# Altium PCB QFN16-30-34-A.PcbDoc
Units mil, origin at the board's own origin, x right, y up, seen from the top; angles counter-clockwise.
Board outline 1200 x 3800 mil, 4 copper layers (Top Layer, Metal 2, Metal 3, Bottom Layer), stack 61.6 mil thick; 25 components, 16 nets, 109 pads, 567 vias.
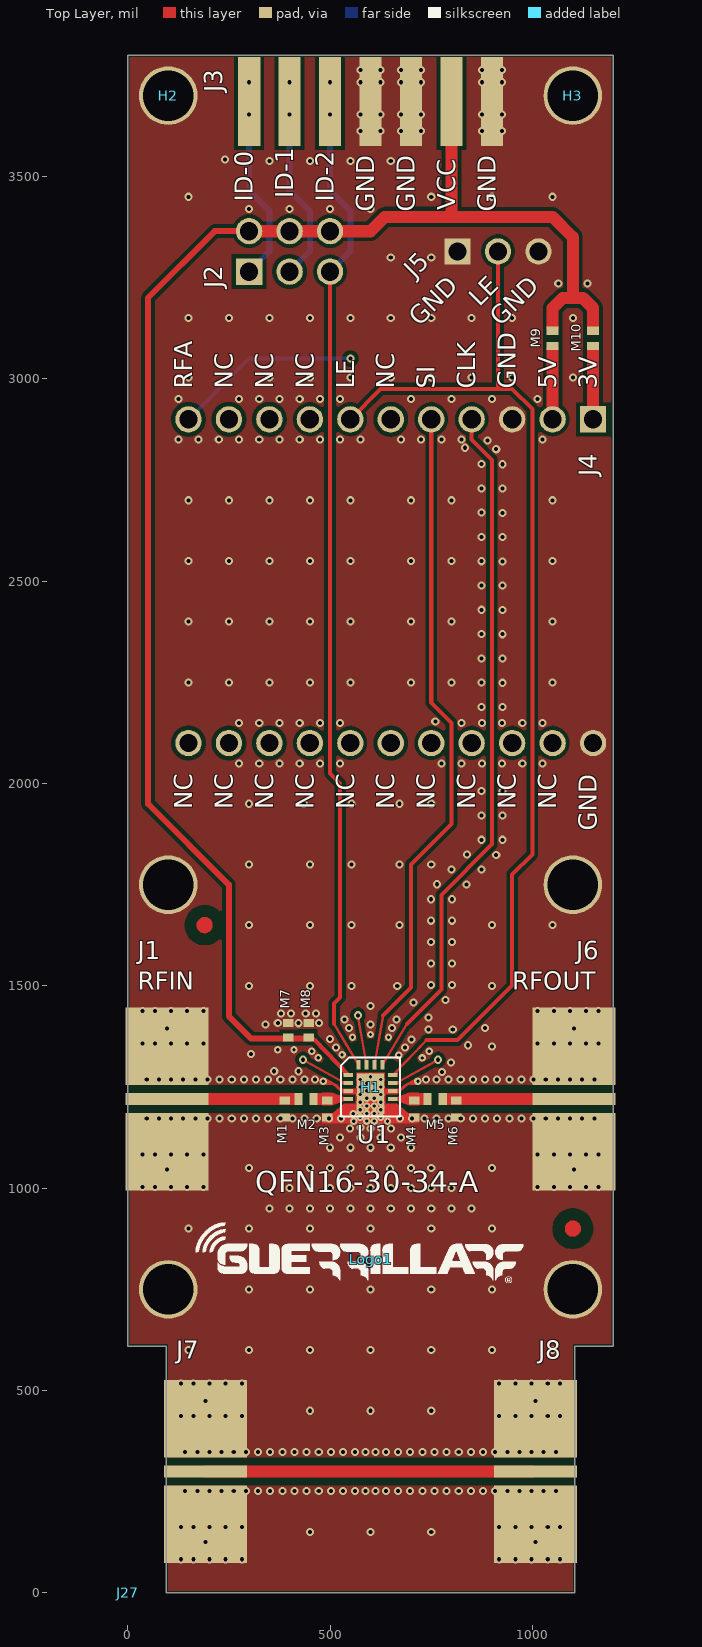
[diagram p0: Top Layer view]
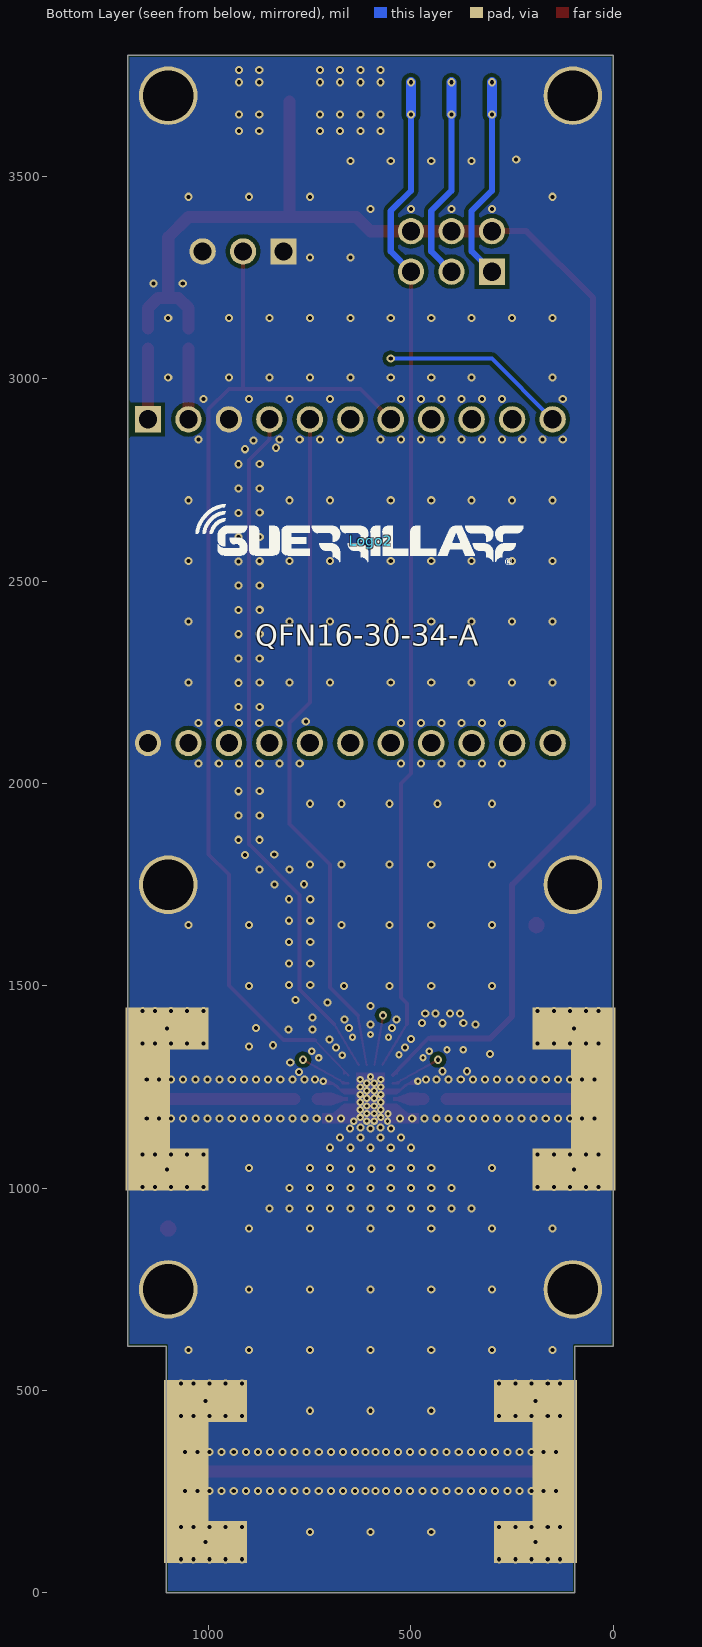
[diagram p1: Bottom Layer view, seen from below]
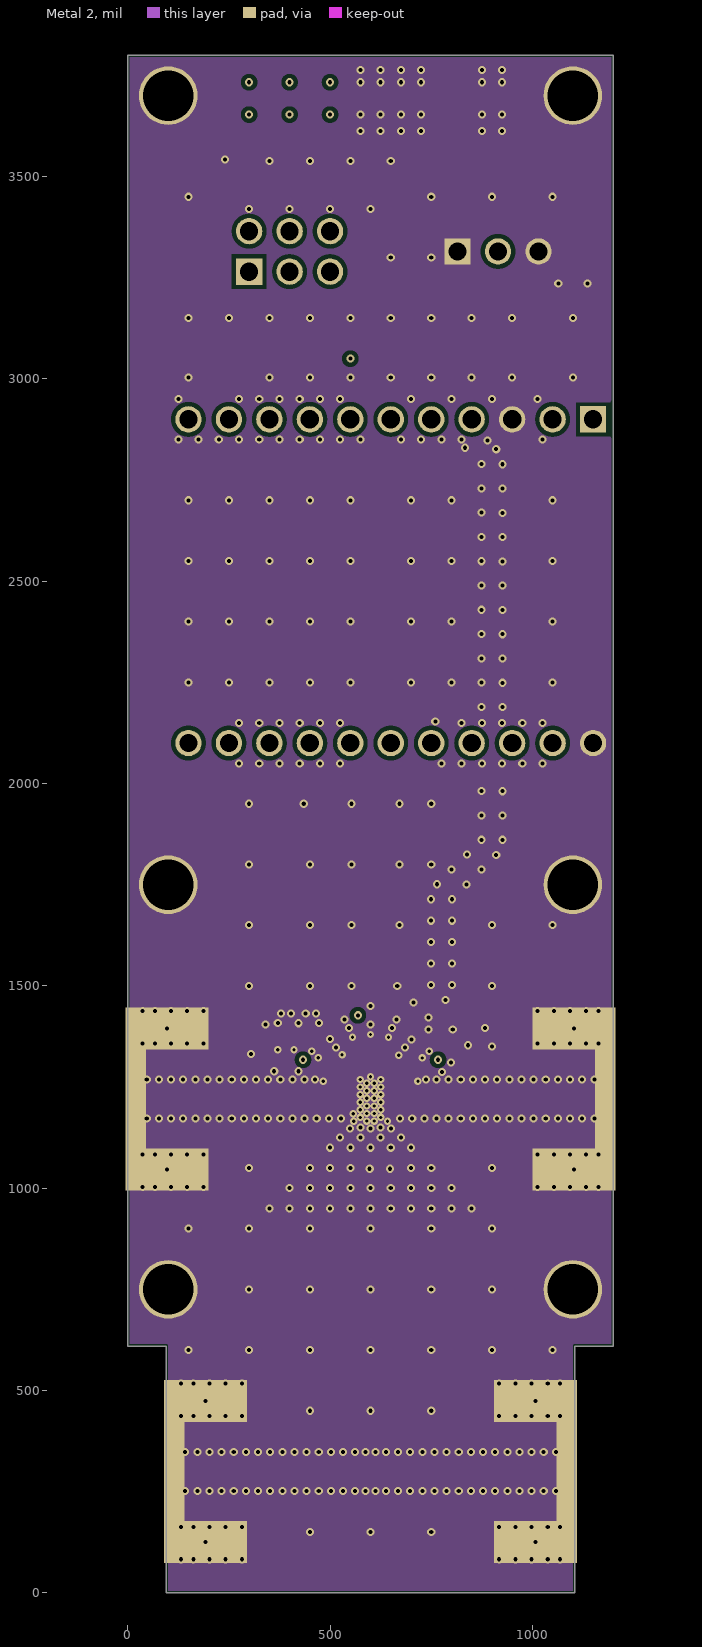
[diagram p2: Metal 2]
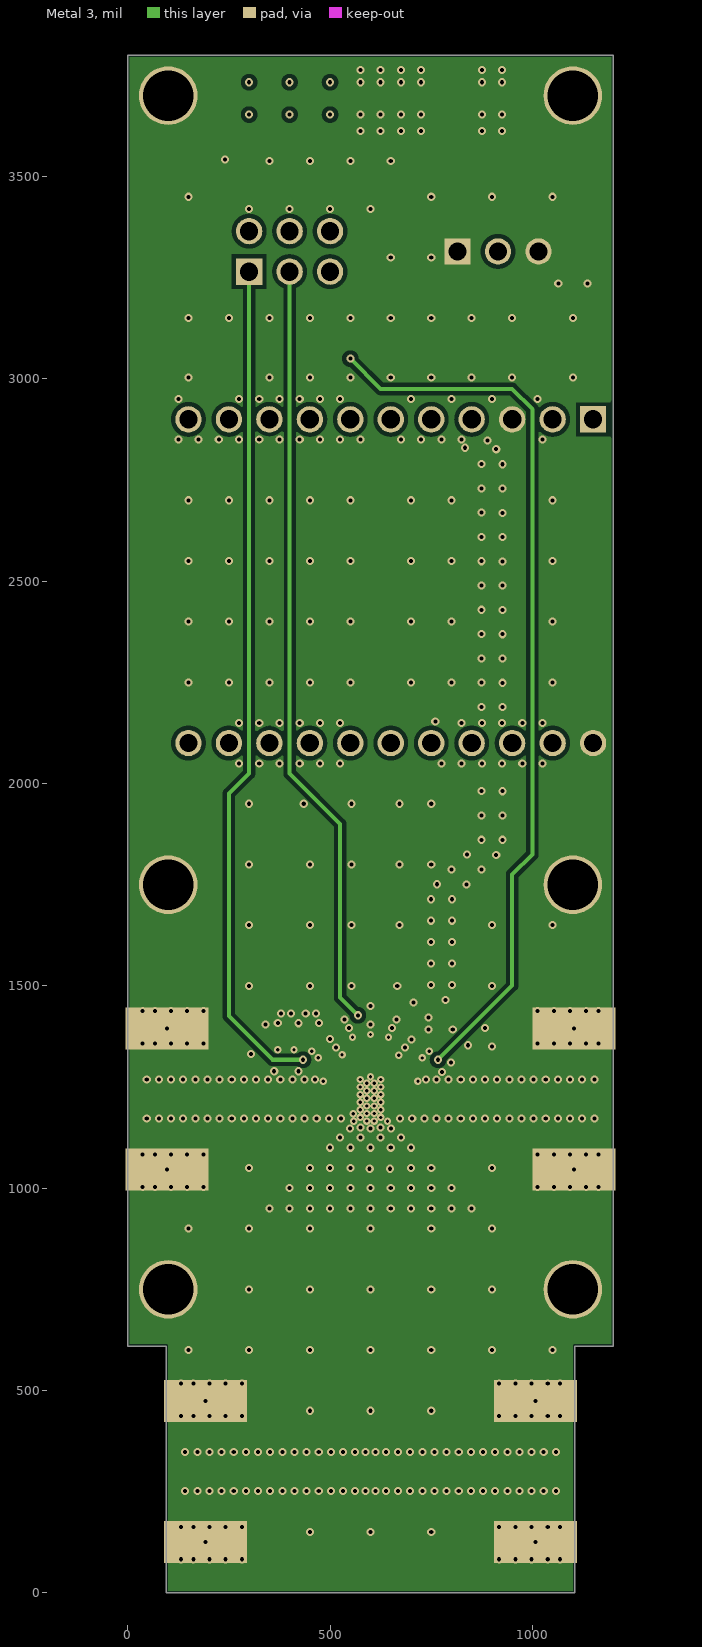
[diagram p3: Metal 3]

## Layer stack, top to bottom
Top Solder: solder mask 0.4, Solder Resist, Dk 3.5
Top Layer: signal copper 1.4
Dielectric 2: core 16, RO4003C, Dk 3.38
Metal 2: signal copper 1.4
Dielectric 1: prepreg 24, FR-4, Dk 4.8
Metal 3: signal copper 1.4
Dielectric 3: core 16, RO4003C, Dk 3.38
Bottom Layer: signal copper 1.4
Bottom Solder: solder mask 0.4, Solder Resist, Dk 3.5

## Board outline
0,610 95,610 95,0 1105,0 1105,610 1200,610 1200,3800 0,3800

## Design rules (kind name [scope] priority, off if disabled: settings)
BackDrilling [IsVia and not InNet('GND')] p1: maxstublength=5 usetopbackdrill=TRUE usebottombackdrill=TRUE holeoversize=10 holetolplus=0.2 holetolminus=0.2
BoardOutlineClearance [All] p1: gap=5 ignorepadtopadclearanceinfootprint=FALSE
Clearance Clearance_I/O [InNetClass('I/O') vs InNet('GND')] p1: gap=7 ignorepadtopadclearanceinfootprint=TRUE
Clearance Clearance_RF [InNetClass('RF') vs InNet('GND')] p2: gap=20 ignorepadtopadclearanceinfootprint=TRUE
Clearance Clearance_GND [InNet('GND')] p3: gap=10 ignorepadtopadclearanceinfootprint=TRUE
Clearance [All] p4: gap=8 ignorepadtopadclearanceinfootprint=TRUE
ComponentClearance ComponentClearance_Heatsink [InComponent('All') And OnLayer('Top Layer') vs HasFootprint('Heatsink_wFid')] p1: gap=0 collisioncheckmode=3 verticalgap=0 showdistances=FALSE
ComponentClearance ComponentClearance_PCB_Frame [InComponent('All') And OnLayer('Top Layer') vs HasFootprint('PCB_Frame')] p2: gap=0 collisioncheckmode=3 verticalgap=0 showdistances=FALSE
ComponentClearance [All] p3: gap=10 collisioncheckmode=3 verticalgap=10 showdistances=TRUE
HoleSize [All] p1: absolutevalues=TRUE maxlimit=125 minlimit=8 maxpercent=80.000 minpercent=20.000
MinimumSolderMaskSliver [All] p1: minsoldermaskwidth=5
PlaneClearance [Not InNet('GND')] p1: clearance=20
PlaneConnect [InNet('GND')] p1: planeconnectstyle=Direct reliefexpansion=20 reliefentries=4 reliefconductorwidth=10 reliefairgap=10
PolygonConnect [All vs InNet('GND')] p1: connectstyle=Direct reliefconductorwidth=10 reliefentries=4 polygonreliefangle="90 Angle" airgapwidth=10
RoutingVias [All] p1: holewidth=10 width=20 viastyle="Through Hole" minholewidth=8 minwidth=18 maxholewidth=23.62 maxwidth=33.62
SilkToSilkClearance [All] p1: silktosilkclearance=5
SilkToSolderMaskClearance [IsPad] p1: minsilkscreentomaskgap=5 clearancetoexposedcopper=TRUE
SolderMaskExpansion [All] p1: expansion=1 istentingtop=FALSE
UnRoutedNet [All] p1: checkbadconnections=TRUE
Width [All] p1: maxlimit=100 minlimit=2 preferedwidth=10
22 further rules are at their usual default settings.

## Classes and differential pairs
net class RF: NetJ1_1 NetJ6_1 NetJ7_1 NetM2_1 NetM4_2

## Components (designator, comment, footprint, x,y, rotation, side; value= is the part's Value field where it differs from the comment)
H1 "Heatsink_wFid" Heatsink_wFid 600,1250 r0 top
H2 "GND_Lug" GND_Lug 100,3700 r0 top
H3 "GND_Lug" GND_Lug 1100,3700 r0 top
J1 "SMA Round_Pin_RevD + HiFreq" "SMA Round_Pin_RevD + HiFreq" 0,1220.47 r0 top
J2 "Header_V_Dual-3-Pin_100MIL" Header_V_Dual-3-Pin_100MIL 400,3315 r90 top
J3 "Header_H_7-Pin_100mil" Header_H_7-Pin_100mil 600,3800 r0 top
J4 "USB_Interface" USB_Interface 650,2500 r270 top
J5 "Header_V_3-Pin_100MIL" Header_V_3-Pin_100MIL 915,3315 r90 top (schematic designator J9)
J6 "SMA Round_Pin_RevD + HiFreq" "SMA Round_Pin_RevD + HiFreq" 1200,1220.47 r180 top (schematic designator J5)
J7 "SMA Round_Pin_RevD + HiFreq" "SMA Round_Pin_RevD + HiFreq" 95,300 r0 top
J8 "SMA Round_Pin_RevD + HiFreq" "SMA Round_Pin_RevD + HiFreq" 1105,300 r180 top (schematic designator J6)
J27 "Comment" PCB_Fab_30T-20G-16D_4003 0,0 r0 top
Logo1 "GRF_2021_Full" GRF_2021_Full 600,825 r0 top
Logo2 "GRF_2021_Full" GRF_2021_Full 600,2600 r180 bottom
M1 "0402_20x26x22" 0402_20x26x22 388.5,1195.47 r90 top
M2 "0402_20x30x18" 0402_20x30x18 440.5,1220.47 r180 top
M3 "0402_20x26x22" 0402_20x26x22 492.5,1195.47 r90 top
M4 "0402_20x26x22" 0402_20x26x22 707.5,1195.47 r90 top
M5 "0402_20x30x18" 0402_20x30x18 759.5,1220.47 r180 top
M6 "0402_20x26x22" 0402_20x26x22 811.5,1195.47 r90 top
M7 "0402_20x26x16" 0402_20x26x16 396.81,1390.2 r270 top
M8 "0402_20x26x16" 0402_20x26x16 446.81,1390.2 r270 top
M9 "0402_23p5x27p5x15p5" 0402_20x30x18 1050,3100 r270 top
M10 "0402_23p5x27p5x15p5" 0402_20x30x18 1150,3100 r270 top
U1 "QFN16_3x3mm_RevG" QFN16_3x3mm_RevG 600,1250 r0 top

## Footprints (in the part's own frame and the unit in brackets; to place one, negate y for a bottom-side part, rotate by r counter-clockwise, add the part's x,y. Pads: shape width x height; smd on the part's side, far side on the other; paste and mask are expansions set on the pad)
0402_20x26x16 [mil] "0402 26mil Wide"
  rect 20x26 smd: 1(-18,0) 2(18,0)
0402_20x26x22 [mil] "0402 RF Shunt 30mil RF"
  rect 20x26 smd: 1(-21,0) 2(21,0)
0402_20x30x18 [mil] "0402 RF Series 30mil RF"
  rect 20x30 smd: 1(-19,0) 2(19,0)
GND_Lug [mil] "Grounding Lug"
  round 145 hole 125 paste-100 mask+20: 1(0,0)
GRF_2021_Full [mil] "2021 Guerrilla RF Logo"
  silkscreen extent -432,-59 378,90
Header_H_7-Pin_100mil [mil] "Generic Flat Header"
  rect 55x220 smd paste-28: 1(-300,-115) 2(-200,-115) 3(-100,-115) 4(0,-115) 5(100,-115) 6(200,-115) 7(300,-115)
Header_V_3-Pin_100MIL [mil] "Generic Vertical Header"
  rect 65x65 hole 45 paste-45: 1(0,100)
  round 65 hole 45 paste-45: 2(0,0) 3(0,-100)
Header_V_Dual-3-Pin_100MIL [mil] "Generic Vertical Header"
  rect 65x65 hole 45 paste-45: 1(-50,100)
  round 65 hole 45 paste-45: 2(50,100) 3(-50,0) 4(50,0) 5(-50,-100) 6(50,-100)
Heatsink_wFid [mil] "Heatsink mounting wFiducials"
  round 145 hole 125 paste-100 mask+12: 1(-500,-500) 1(-500,500) 1(500,-500) 1(500,500)
  Top Layer circle w20: c500,-350 r10
  Top Layer circle w20: c-410,400 r10
  Top Layer pour cut-out: -460,400 -456.19,419.13 -445.36,435.36 -429.13,446.19 -410,450 -410,450 -390.87,446.19 -374.64,435.36 -363.81,419.13 -360,400 -360,400 -363.81,380.87 -374.64,364.64 -390.87,353.81 -410,350 -410,350 -429.13,353.81 -445.36,364.64 -456.19,380.87 -460,400
  Top Layer pour cut-out: 500,-400 480.87,-396.19 464.64,-385.36 453.81,-369.13 450,-350 450,-350 453.81,-330.87 464.64,-314.64 480.87,-303.81 500,-300 500,-300 519.13,-303.81 535.36,-314.64 546.19,-330.87 550,-350 550,-350 546.19,-369.13 535.36,-385.36 519.13,-396.19 500,-400
PCB_Fab_30T-20G-16D_4003 [mil] "STD RF&Stack  30mil RF 20mil Gap  16mil Dielectric"
QFN16_3x3mm_RevG [mm] "Standard Footprint (Amkor-J / Unisem)"
  rect 0.6x0.25 smd paste-100: 1(-1.4,0.75) 2(-1.4,0.25) 3(-1.4,-0.25) 4(-1.4,-0.75) 9(1.4,-0.75) 10(1.4,-0.25) 11(1.4,0.25) 12(1.4,0.75)
  rect 0.25x0.6 smd paste-100: 5(-0.75,-1.4) 6(-0.25,-1.4) 7(0.25,-1.4) 8(0.75,-1.4) 13(0.75,1.4) 14(0.25,1.4) 15(-0.25,1.4) 16(-0.75,1.4)
  rect 1.7x1.7 smd paste-100: 17(0,0)
  silkscreen extent -1.84,-1.84 1.84,1.84
"SMA Round_Pin_RevD + HiFreq" [mil] "142-0701-801 / 142-0761-861"
  rect 205x30 smd paste-30: 1(97.5,0)
  rect 50x290 on Mid1 paste-50: 2(20,0)
  rect 110x280 smd far side paste-100: 2(50,0)
  rect 205x104 hole 10 paste-100: 2(97.5,-174) 2(97.5,174)
  rect 205x100 smd paste-100: 2(97.5,-85) 2(97.5,85)
USB_Interface [mil] "FT232H USB Interface"
  rect 65x65 hole 45 paste-45: 1(-400,500)
  round 65 hole 45 paste-45: 2(-400,400) 3(-400,300) 4(-400,200) 5(-400,100) 6(-400,0) 7(-400,-100) 8(-400,-200) 9(-400,-300) 10(-400,-400) 11(-400,-500) 12(400,-500) 13(400,-400) 14(400,-300) 15(400,-200) 16(400,-100) 17(400,0) 18(400,100) 19(400,200) 20(400,300) 21(400,400) 22(400,500)

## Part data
H1 H2 H3: library part "Mounting Holes"
J1 J6 J7 J8: library part RF_Conn
J2: library part Header_Dual-3-Pin, "Header 6-Pin"
J3: library part Header_7-Pin, "Header 7-Pin"
J4: "FT232H USB Interface"
J5: library part Header_3-Pin, "Header 3-Pin"
Logo1 Logo2: library part GRF_Logo, "GRF_Logo"
M1 M2 M3 M4 M5 M6 M7 M8: library part Capacitor
M9 M10: library part Resistor
U1: library part QFN16_3x3mm, "QFN16_3x3mm"

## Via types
v1: diameter 20/20/20/20 (per signal layer), hole 10, Top Layer to Bottom Layer, tented both sides, 443 vias
v2: diameter 20, hole 10, Top Layer to Bottom Layer, 80 vias
v3: diameter 18/18/18/18 (per signal layer), hole 8, Top Layer to Bottom Layer, tented both sides, 41 vias
v4: diameter 20/20/20/20 (per signal layer), hole 10.01, Top Layer to Bottom Layer, tented both sides, 3 vias

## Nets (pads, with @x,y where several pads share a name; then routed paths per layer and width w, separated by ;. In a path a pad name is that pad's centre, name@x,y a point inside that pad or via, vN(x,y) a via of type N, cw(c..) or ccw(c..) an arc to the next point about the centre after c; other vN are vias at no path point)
"CLK serial": J4.4 U1.13 | length 1719.3
  Top Layer w6: U1.13 690,1405.88
  Top Layer w10: 690,1405.88 775,1490.88 775,1725 900,1850 900,2800 850,2850 J4.4
GND: H1.1 H2.1 H3.1 J1.2 J3.4 J3.5 J3.7 J4.3 J4.22 J5.1 J5.3 J6.2 J7.2 J8.2 M1.1 M3.1 M4.1 M6.1 M7.1 M8.1 U1.3 U1.5 U1.6 U1.7 U1.8 U1.10 U1.17
  other v1: 450,150 600,150 750,150 142,252 172,252 202,252 232,252 262,252 292,252 322,252 352,252 382,252 412,252 442,252 472,252 502,252 532,252 562,252 588,252 612,252 638,252 668,252 698,252 728,252 758,252 788,252 818,252 848,252 878,252 908,252 938,252 968,252 998,252 1028,252 1058,252 142,348 172,348 202,348 232,348 262,348 292,348 322,348 352,348 382,348 412,348 442,348 472,348 502,348 532,348 562,348 588,348 612,348 638,348 668,348 698,348 728,348 758,348 788,348 818,348 848,348 878,348 908,348 938,348 968,348 998,348 1028,348 1058,348 450,450 600,450 750,450 150,600 300,600 450,600 600,600 750,600 900,600 1050,600 300,750 450,750 600,750 750,750 900,750 150,900 300,900 450,900 600,900 750,900 900,900 350,950 400,950 450,950 500,950 550,950 600,950 650,950 700,950 750,950 800,950 850,950 400,1000 450,1000 500,1000 550,1000 600,1000 650,1000 700,1000 750,1000 800,1000 598,1048 648,1048 300,1050 450,1050 500,1050 550,1050 700,1050 750,1050 900,1050 500,1100 550,1100 600,1100 650,1100 700,1100 525,1125 575,1125 625,1125 675,1125 549,1148 600,1148 651,1148 575,1150 625,1150 47,1172.47 77,1172.47 107,1172.47 137,1172.47 167,1172.47 197,1172.47 227,1172.47 257,1172.47 287,1172.47 317,1172.47 347,1172.47 377,1172.47 407,1172.47 437,1172.47 467,1172.47 497,1172.47 527,1172.47 673,1172.47 703,1172.47 733,1172.47 763,1172.47 793,1172.47 823,1172.47 853,1172.47 883,1172.47 913,1172.47 943,1172.47 973,1172.47 1003,1172.47 1033,1172.47 1063,1172.47 1093,1172.47 1123,1172.47 1153,1172.47 47,1268.47 77,1268.47 107,1268.47 137,1268.47 167,1268.47 197,1268.47 227,1268.47 257,1268.47 287,1268.47 317,1268.47 347,1268.47 377,1268.47 407,1268.47 437,1268.47 463,1268.47 737,1268.47 763,1268.47 793,1268.47 823,1268.47 853,1268.47 883,1268.47 913,1268.47 943,1268.47 973,1268.47 1003,1268.47 1033,1268.47 1063,1268.47 1093,1268.47 1123,1268.47 1153,1268.47 776.86,1287.2 362,1289 422,1289 798.45,1310.77 305,1331.43 514.71,1348.11 685.29,1348.11 900,1350 840.88,1353.2 701.18,1367.42 499.85,1368.3 743.18,1392 803.18,1392 546.99,1395.65 653.01,1395.65 883.31,1395.62 340.81,1404.7 600,1405 421.81,1407.7 370.81,1408.7 472.81,1408.7 536.02,1416.64 663.98,1416.64 743.18,1422.3 378.81,1431.2 403.81,1431.2 439.81,1431.2 464.81,1431.2 600,1450 706.41,1459.06 785.61,1464.72 300,1500 450,1500 553,1500 666,1500 900,1500 749,1501.88 801,1501.88 749,1554.91 801,1554.91 749,1607.94 801,1607.94 300,1650 450,1650 553,1650 672,1650 900,1650 1050,1650 749,1660.97 801,1660.97 749,1714 801,1714 837.02,1750.1 764.39,1751.16 800.42,1787.26 874.58,1787.74 300,1800 450,1800 553,1800 672,1800 750,1800 910.61,1823.84 837.98,1824.9 874,1861 926,1861 873.84,1921.39 926,1921 300,1950 435,1950 553,1950 672,1950 750,1950 873.84,1981.39 926,1981 275,2050 325,2050 375,2050 425,2050 475,2050 525,2050 775,2050 825,2050 875,2050 925,2050 975,2050 1025,2050 275,2150 325,2150 375,2150 425,2150 475,2150 525,2150 825,2150 875,2150 925,2150 975,2150 1025,2150 760,2153 873.84,2189.39 926,2189 873.84,2249.39 926,2249 150,2250 250,2250 350,2250 450,2250 550,2250 700,2250 800,2250 1050,2250 873.84,2309.39 926,2309 873.84,2369.39 926,2369 150,2400 250,2400 350,2400 450,2400 550,2400 700,2400 800,2400 1050,2400 873.84,2429.39 926,2429 873.84,2489.39 926,2489 873.84,2549.39 926,2549 150,2550 250,2550 350,2550 450,2550 550,2550 700,2550 800,2550 1050,2550 873.84,2609.39 926,2609 873.84,2669.39 926,2669 150,2700 250,2700 350,2700 450,2700 550,2700 700,2700 800,2700 1050,2700 873.84,2729.39 926,2729 873.84,2789.39 926,2789 910.61,2826.16 833.41,2829.82 889.39,2847.38 125,2850 175,2850 225,2850 275,2850 325,2850 375,2850 425,2850 475,2850 525,2850 575,2850 675,2850 725,2850 775,2850 825,2850 1025,2850 125,2950 275,2950 325,2950 375,2950 425,2950 475,2950 525,2950 700,2950 800,2950 900,2950 1013,2950 150,3003 350,3003 450,3003 550,3003 650,3003 750,3003 850,3003 950,3003 1100,3003 150,3150 250,3150 350,3150 450,3150 550,3150 650,3150 750,3150 850,3150 950,3150 1100,3150 1064,3236 1136,3236 650,3300 750,3300 300,3420 400,3420 500,3420 600,3420 150,3450 750,3450 900,3450 1050,3450 350,3538 450,3538 550,3538 650,3538 240,3542 575,3613 625,3613 675,3613 725,3613 875,3613 925,3613 575,3653 625,3653 675,3653 725,3653 875,3653 925,3653 575,3733 625,3733 675,3733 725,3733 875,3733 925,3733 575,3763 625,3763 675,3763 725,3763 875,3763 925,3763
  other v2: 132,83 162,83 202,83 242,83 282,83 918,83 958,83 998,83 1038,83 1068,83 132,163 162,163 202,163 242,163 282,163 918,163 958,163 998,163 1038,163 1068,163 132,437 162,437 202,437 242,437 282,437 918,437 958,437 998,437 1038,437 1068,437 132,517 162,517 202,517 242,517 282,517 918,517 958,517 998,517 1038,517 1068,517 37,1003.47 67,1003.47 107,1003.47 147,1003.47 187,1003.47 1013,1003.47 1053,1003.47 1093,1003.47 1133,1003.47 1163,1003.47 37,1083.47 67,1083.47 107,1083.47 147,1083.47 187,1083.47 1013,1083.47 1053,1083.47 1093,1083.47 1133,1083.47 1163,1083.47 37,1357.47 67,1357.47 107,1357.47 147,1357.47 187,1357.47 1013,1357.47 1053,1357.47 1093,1357.47 1133,1357.47 1163,1357.47 37,1437.47 67,1437.47 107,1437.47 147,1437.47 187,1437.47 1013,1437.47 1053,1437.47 1093,1437.47 1133,1437.47 1163,1437.47
  other v3: 558.25,1165.5 590.75,1165.75 609.25,1165.75 641.75,1165.5 574.5,1175 625.5,1175 557,1184 590.75,1184.5 609.25,1184.5 574.5,1193.75 625.5,1193.75 590.75,1203.25 609.25,1203.25 574.5,1212.5 625.5,1212.5 590.75,1222 609.25,1222 574.5,1231.25 625.5,1231.25 590.75,1240.75 609.25,1240.75 574.5,1250 625.5,1250 590.75,1259.25 609.25,1259.25 483,1264.5 717,1264.5 574.5,1268.75 625.5,1268.75 600,1275.5 470.53,1322.16 728,1322 669.92,1328.34 529.77,1329.94 454.93,1338.16 745.07,1338.16 371,1342.25 411,1342.25 555.54,1373.25 644.46,1373.25 600,1380
"ID0 address": J2.1 J3.1 U1.2 | length 2772.5
  Top Layer w6: v4(433.11,1317.43) 492.2,1284.65 525.16,1266.37 531.68,1259.84 U1.2
  Metal 3 w10: J2.1 300,2025 250,1975 250,1425 357.57,1317.43 v4(433.11,1317.43)
  Bottom Layer w15: J2.1 350,3315 350,3415 300,3465 v1(300,3653) 300,3700
  Bottom Layer w25: v1(300,3653) v1(300,3733)
"ID1 address": J2.3 J3.2 U1.15 | length 2588.1
  Top Layer w6: v4(568.74,1427.27) U1.15
  Metal 3 w10: J2.3 400,2700 400,2025 525,1900 525,1471.01 v4(568.74,1427.27)
  Bottom Layer w15: J2.3 450,3315 450,3415 400,3465 v1(400,3653) 400,3700
  Bottom Layer w25: v1(400,3653) v1(400,3733)
"ID2 address": J2.5 J3.3 U1.16 | length 2549.6
  Top Layer w6: 510,1405.88 537.66,1359.8 U1.16
  Top Layer w10: J2.5 500,2025 525,2000 525,1471.01 510,1456.01 510,1405.88
  Bottom Layer w15: J2.5 550,3315 550,3415 500,3465 v1(500,3653) 500,3700
  Bottom Layer w25: v1(500,3653) v1(500,3733)
"LE    serial": J4.7 J5.2 U1.12 | length 2677.6
  Top Layer w6: U1.12 737.89,1365.7 ; 915,2977.28 917.28,2975
  Top Layer w10: J4.7 625,2975 917.28,2975 950,2975 1000,2925 1000,1825 950,1775 950,1500.54 815.17,1365.7 737.89,1365.7 ; 915,2975 J5.2
NetJ1_1: J1.1 M1.2 M2.2 | length 311.5
  Top Layer w30: J1.1@100,1220.47 388.5,1220.47 M2.2@411.5,1220.47
NetJ4_1: J4.1 M10.2 | length 175
  Top Layer w30: J4.1 M10.2@1150,3075
NetJ4_2: J4.2 M9.2 | length 175
  Top Layer w30: J4.2 M9.2@1050,3075
NetJ6_1: J6.1 M5.1 M6.2 | length 361.5
  Top Layer w30: 788.5,1220.47 J6.1 J6.1@1150,1220.47
NetJ7_1: J7.1 J8.1 | length 807.5
  Top Layer w30: J7.1 J8.1@1000,300
NetM2_1: M2.1 M3.2 U1.4 | length 30.5
  Top Layer w30: 469.5,1220.47 M3.2@500,1220.47
NetM4_2: M4.2 M5.2 U1.9 | length 24.7
  Top Layer w10: M4.2 M4.2@711.5,1220.47
  Top Layer w30: M4.2@711.5,1220.47 M5.2@730.5,1220.47
RFA: J4.11 U1.11 | length 2795.7
  Top Layer w6: U1.11 668.32,1259.84 674.84,1266.37 v4(766.89,1317.43)
  Metal 3 w10: v1(550,3050) 625,2975 950,2975 1000,2925 1000,1825 950,1775 950,1500.54 v4(766.89,1317.43)
  Bottom Layer w10: J4.11 300,3050 v1(550,3050)
"SI     serial": J4.5 U1.14 | length 1687.4
  Top Layer w6: U1.14 625.2,1392.72 631.26,1427.27
  Top Layer w10: 631.26,1427.27 700,1496.01 700,1800 800,1900 800,2150 750,2200 J4.5
VCC: J2.2 J2.4 J2.6 J3.6 M7.2 M8.2 M9.1 M10.1 U1.1 | length 4017.6
  Top Layer w10: M8.2@456.38,1371.44 462.11,1365.7 U1.1
  Top Layer w15: J2.2 215,3365 50,3200 50,1950 250,1750 250,1425 305.3,1369.7 M8.2@450,1369.7
  Top Layer w30: J2.2 600,3365 635,3400 800,3400 ; J3.6 800,3400 ; M9.1@1050,3125 1050,3175 1075,3200 1100,3200 ; M10.1@1150,3125 1150,3175 1125,3200 1100,3200 ; 800,3400 1050,3400 1100,3350 1100,3200
pads on no net: J4.6 J4.8 J4.9 J4.10 J4.12 J4.13 J4.14 J4.15 J4.16 J4.17 J4.18 J4.19 J4.20 J4.21

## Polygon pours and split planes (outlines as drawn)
no net on Bottom Solder "NONET_L-01_P-001" (solid): -3,2000 -3,1460 211,1460 211,1331 116,1331 116,1109 211,1109 211,983 -3,983 -3,610 92,610 92,538 306,538 306,411 211,411 211,189 306,189 306,62 92,62 92,0 1102,0 1102,62 894,62 894,189 989,189 989,411 894,411 894,538 1102,538 1102,610 1197,610 1197,982 989,982 989,1109 1084,1109 1084,1330 989,1330 989,1459 1197,1459 1197,2000
GND on Bottom Layer "GND_L04_P001" (solid, pour order 1): 0,0 1200,0 1200,3800 0,3800
GND on Metal 2 "NONET_L-01_P-001" (solid, pour order 2): 0,0 1200,0 1200,3800 0,3800
GND on Metal 3 "NONET_L-01_P-001" (solid, pour order 3): 0,0 1200,0 1200,3800 0,3800
GND on Top Layer "GND_L01_P000" (solid, pour order 0): 0,0 1200,0 1200,3800 0,3800

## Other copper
Top Layer:
  region net "ID0 address": 534.68,1264.76 528.68,1264.76 528.68,1259.84 534.68,1259.84
  region net VCC: 533.07,1281.45 533.07,1287.45 537.99,1287.45 537.99,1281.45
  region net RFA: 665.32,1264.76 671.32,1264.76 671.32,1259.84 665.32,1259.84
  region net "LE    serial": 662.01,1281.45 662.01,1287.45 666.93,1287.45 666.93,1281.45
  pour cut-out: 473.14,1296.17 483.09,1317.5 496.58,1336.78 531.06,1307.85 542.15,1318.94 555,1327.94 540,1353.92 558.96,1362.76 579.16,1368.18 600,1370 620.84,1368.18 641.04,1362.76 660,1353.92 645,1327.94 657.85,1318.94 668.94,1307.85 703.42,1336.78 716.91,1317.5 726.86,1296.17
  region net GND: 480.28,1255.47 480.28,1271.65 488.83,1271.65 517.25,1255.89 526.75,1246 565,1246 565,1285 635,1285 635,1246 673.25,1246 682.75,1255.89 711.17,1271.65 719.72,1271.65 719.72,1255.47 693.22,1255.47 665.6,1232.46 636.24,1232.46 636.24,1208.49 665.6,1208.49 693.22,1185.47 719.72,1185.47 719.72,1160 480.28,1160 480.28,1185.47 506.78,1185.47 534.4,1208.49 563.76,1208.49 563.76,1232.46 534.4,1232.46 506.78,1255.47
  region net NetM4_2: 656.12,1224.41 664.28,1224.41 694.28,1235.47 719.72,1235.47 719.72,1205.47 694.28,1205.47 664.28,1216.54 656.12,1216.54
  region net NetM2_1: 543.88,1224.41 535.72,1224.41 505.72,1235.47 480.28,1235.47 480.28,1205.47 505.72,1205.47 535.72,1216.54 543.88,1216.54

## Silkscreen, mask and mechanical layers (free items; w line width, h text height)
Top Overlay:
  text "ID-1" at 424.12,3446.81 h75 r90
  text "ID-0" at 323.7,3437.64 h75 r90
  text "ID-2" at 524.12,3437.99 h75 r90
  text "VCC" at 824.01,3416.27 h75 r90
  text "GND" at 624.01,3413.01 h75 r90
  text "GND" at 724.01,3413.01 h75 r90
  text "GND" at 924.01,3413.01 h75 r90
  text "LE" at 879.96,3166 h75 r45
  text "GND" at 731.58,3117.62 h75 r45
  text "GND" at 931.58,3117.62 h75 r45
  text "RFA" at 174.01,2975 h75 r90
  text "NC" at 274.01,2975 h75 r90
  text "NC" at 374.01,2975 h75 r90
  text "NC" at 474.01,2975 h75 r90
  text "LE" at 574.01,2975 h75 r90
  text "NC" at 674.01,2975 h75 r90
  text "SI" at 774.01,2975 h75 r90
  text "CLK" at 874.01,2975 h75 r90
  text "GND" at 974.01,2975 h75 r90
  text "5V" at 1073.6,2975 h75 r90
  text "3V" at 1173.7,2975 h75 r90
  text "NC" at 174.01,1935.89 h75 r90
  text "NC" at 274.01,1935.89 h75 r90
  text "NC" at 374.01,1935.89 h75 r90
  text "NC" at 474.01,1935.89 h75 r90
  text "NC" at 574.01,1935.89 h75 r90
  text "NC" at 674.01,1935.89 h75 r90
  text "NC" at 774.01,1935.89 h75 r90
  text "NC" at 874.01,1935.89 h75 r90
  text "NC" at 974.01,1935.89 h75 r90
  text "NC" at 1074.01,1935.89 h75 r90
  text "GND" at 1174.01,1883.01 h75 r90
  text "RFIN" at 25,1475.99 h75
  text "RFOUT" at 950.56,1475.99 h75
  text "QFN16-30-34-A" at 315.16,972.93 h90
Bottom Overlay:
  text "QFN16-30-34-A" at 884.84,2322.93 h90
Board_Dimension:
  the board outline again, w10
Drill Drawing:
  lines w10: -1432.71,4202.5 -1366.04,4202.5 -1366.04,4269.17 -1432.71,4269.17 -1432.71,4202.5
  lines w15: -1492.5,-2842.5 4147.18,-2842.5 ; -1492.5,-2092.5 4147.18,-2092.5 ; -1492.5,4157.5 4147.18,4157.5 ; -1492.5,4307.5 4147.18,4307.5 ; -857.5,-2992.5 -857.5,-1942.5 ; -857.5,4007.5 -857.5,4457.5 ; -267.5,-2992.5 -267.5,-1942.5 ; -267.5,4007.5 -267.5,4457.5 ; 1022.5,-2992.5 1022.5,-1942.5 ; 1022.5,4007.5 1022.5,4457.5 ; 1528.38,-2992.5 1528.38,-1942.5 ; 1528.38,4007.5 1528.38,4457.5 ; 2262.18,-2992.5 2262.18,-1942.5 ; 2262.18,4007.5 2262.18,4457.5 ; -1492.5,-2992.5 4147.18,-2992.5 4147.18,-1942.5 -1492.5,-1942.5 -1492.5,-2992.5 ; -1492.5,4007.5 4147.18,4007.5 4147.18,4457.5 -1492.5,4457.5 -1492.5,4007.5
  text "Symbol" at -1402.5,4352.5 h72
  text "Count" at -812.5,4352.5 h72
  text "Hole Size" at -222.5,4352.5 h72
  text "Plated" at 1067.5,4352.5 h72
  text "Hole Type" at 1573.38,4352.5 h72
  text "Drill Layer Pair" at 2307.18,4352.5 h72
  text "3" at -812.5,4202.5 h60
  text "20.01mil (0.508mm)" at -222.5,4202.5 h60
  text "NPTH" at 1067.5,4202.5 h60
  text "Round" at 1573.38,4202.5 h60
  text "[BD] Metal 3 - Bottom Layer" at 2307.18,4202.5 h60
  text "3 Total" at -812.5,4052.5 h60
  text "Symbol" at -1402.5,-2047.5 h72
  text "Count" at -812.5,-2047.5 h72
  text "Hole Size" at -222.5,-2047.5 h72
  text "Plated" at 1067.5,-2047.5 h72
  text "Hole Type" at 1573.38,-2047.5 h72
  text "Drill Layer Pair" at 2307.18,-2047.5 h72
  text "41" at -812.5,-2197.5 h60
  text "8.00mil (0.203mm)" at -222.5,-2197.5 h60
  text "PTH" at 1067.5,-2197.5 h60
  text "Round" at 1573.38,-2197.5 h60
  text "Top Layer - Bottom Layer" at 2307.18,-2197.5 h60
  text "A" at -1431.59,-2207.49 h66.67
  text "531" at -812.5,-2347.5 h60
  text "10.00mil (0.254mm)" at -222.5,-2347.5 h60
  text "PTH" at 1067.5,-2347.5 h60
  text "Round" at 1573.38,-2347.5 h60
  text "Top Layer - Bottom Layer" at 2307.18,-2347.5 h60
  text "B" at -1431.59,-2357.49 h66.67
  text "3" at -812.5,-2497.5 h60
  text "10.01mil (0.254mm)" at -222.5,-2497.5 h60
  text "PTH" at 1067.5,-2497.5 h60
  text "Round" at 1573.38,-2497.5 h60
  text "Top Layer - Bottom Layer" at 2307.18,-2497.5 h60
  text "C" at -1431.59,-2507.49 h66.67
  text "31" at -812.5,-2647.5 h60
  text "45.00mil (1.143mm)" at -222.5,-2647.5 h60
  text "PTH" at 1067.5,-2647.5 h60
  text "Round" at 1573.38,-2647.5 h60
  text "Top Layer - Bottom Layer" at 2307.18,-2647.5 h60
  text "J" at -1431.59,-2657.49 h66.67
  text "6" at -812.5,-2797.5 h60
  text "125.00mil (3.175mm)" at -222.5,-2797.5 h60
  text "PTH" at 1067.5,-2797.5 h60
  text "Round" at 1573.38,-2797.5 h60
  text "Top Layer - Bottom Layer" at 2307.18,-2797.5 h60
  text "H" at -1431.59,-2807.49 h66.67
  text "612 Total" at -812.5,-2947.5 h60
Document:
  lines w10: -349.16,2596.85 -49.16,1359.79 ; -299.48,2898.88 766.89,1317.43 ; -254.34,-341.59 45.66,176.34 ; -24.16,971.85 -49.16,971.85 -49.16,1446.85 -24.16,1446.85 ; 70.66,58.41 45.66,58.41 45.66,533.41 70.66,533.41 ; 292.21,1220.47 1500,500 ; 433.11,1317.43 -300,2900 568.74,1427.27 ; 480.28,1220.47 1500,500 ; 627.85,300 1500,500 ; 719.72,1220.47 1500,500 ; 884.76,1220.47 1500,500 ; 1132.29,55.64 1157.29,55.64 1157.29,530.64 1132.29,530.64 ; 1157.29,170.3 1482.29,-344.36 ; 1225.84,971.85 1250.84,971.85 1250.84,1446.85 1225.84,1446.85 ; 1250.84,1372.81 1600.84,2596.85
  text "Note C" at -715,2809.9 h125
  text "Note B" at 1632.29,2564.97 h125
  text "Note B" at -727.66,2559.33 h125
  text "Note A" at 1550,404.95 h125
  text "Note B" at 1532.29,-435.03 h125
  text "Note B" at -604.34,-638.47 h125

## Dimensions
0,0 to 100,750 on Mechanical 16
0,0 to 100,1750 on Mechanical 16
0,3800 to 0,0 on Mechanical 16
0,610 to 100,750 on Mechanical 16
0,610 to 1100,750 on Mechanical 16
0,610 to 1200,610 on Mechanical 16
